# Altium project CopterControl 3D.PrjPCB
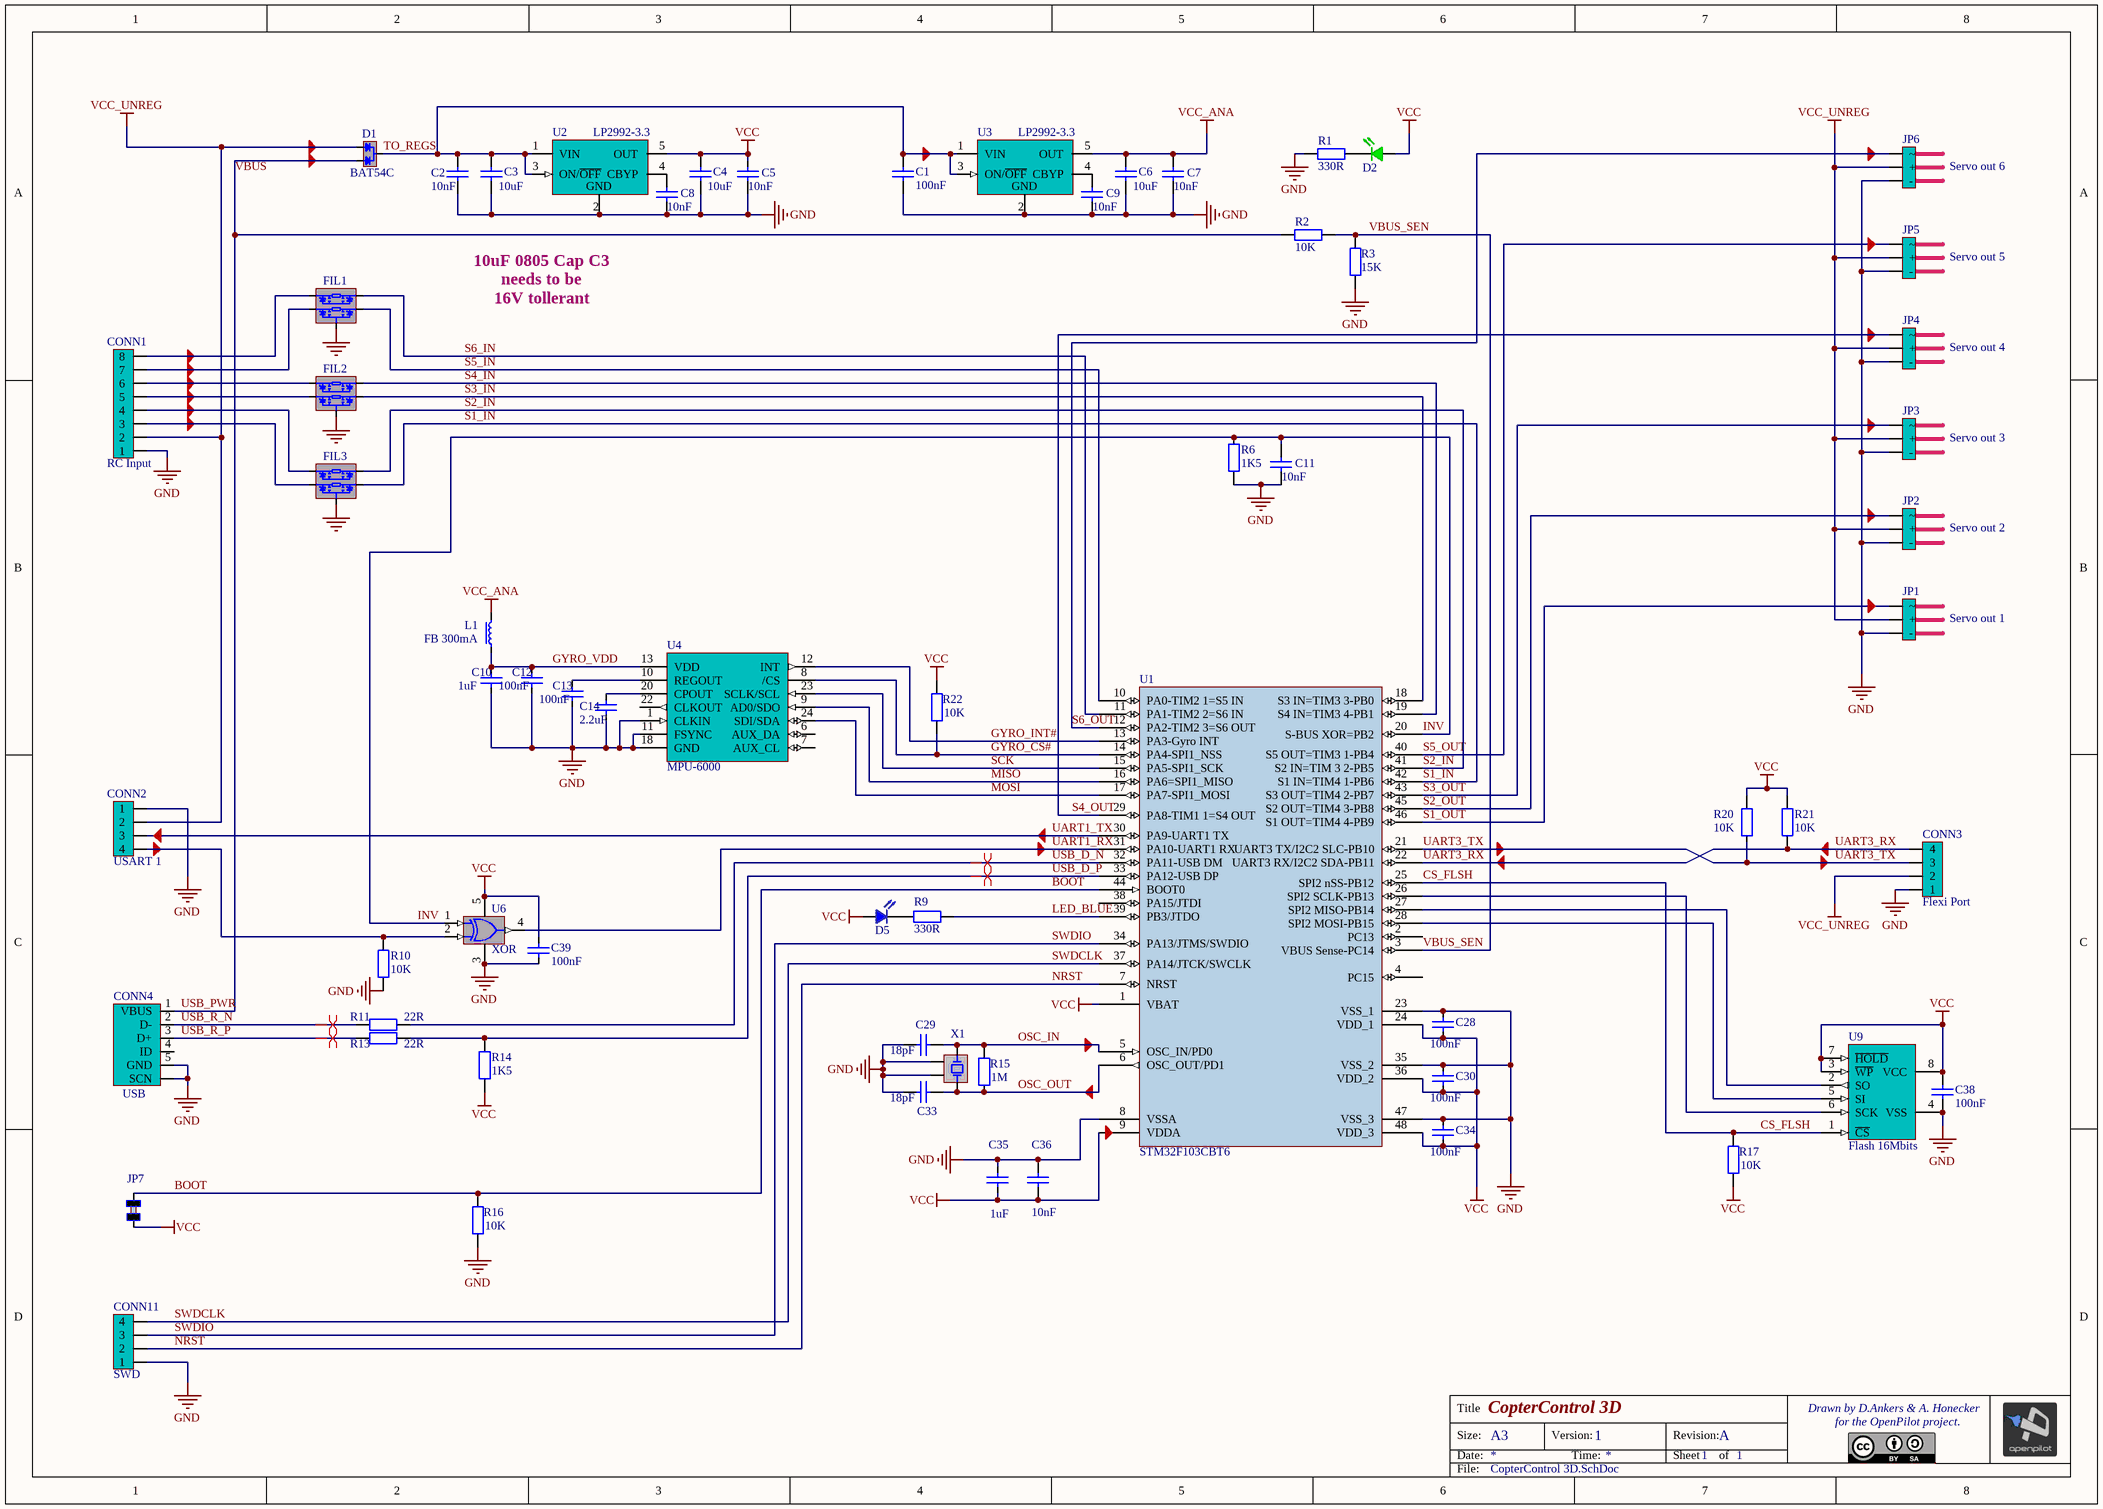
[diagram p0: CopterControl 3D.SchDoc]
1 sheet, 64 parts. Net scope: global (net labels, ports and power ports of the same name join across sheets).
Board file: CopterControl 3D.PcbDoc

## Sheet CopterControl 3D.SchDoc: CopterControl 3D
size A3; Author: David Ankers; DrawnBy: David Ankers; Engineer: David Ankers; Organization: The OpenPilot Project; DocumentNumber: 1; Revision: A; SheetNumber: 1; SheetTotal: 1; License: Creative Commons BY-SA

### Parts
C1  value 100nF  [CAP603N]  (hidden comment: Cap603)
C2  value 10nF  [CAP603L]  (hidden comment: Cap603)
C3  value 10uF  [CAP805L]  (hidden comment: Cap805)
C4  value 10uF  [CAP805L]  (hidden comment: Cap805)
C5  value 10nF  [CAP603N]  (hidden comment: Cap603)
C6  value 10uF  [CAP805L]  (hidden comment: Cap805)
C7  value 10nF  [CAP603N]  (hidden comment: Cap603)
C8  value 10nF  [CAP603N]  (hidden comment: Cap603)
C9  value 10nF  [CAP603N]  (hidden comment: Cap603)
C10  value 1uF  [CAP603L]  (hidden comment: Cap603)
C11  value 10nF  [CAP603N]  (hidden comment: Cap603)
C12  value 100nF  [CAP603L]  (hidden comment: Cap603)
C13  value 100nF  [CAP603L]  (hidden comment: Cap603)
C14  value 2.2uF  [CAP603L]  (hidden comment: Cap603)
C28  value 100nF  [CAP603N]  (hidden comment: Cap603)
C29  value 18pF  [CAP603N]  (hidden comment: Cap603)
C30  value 100nF  [CAP603N]  (hidden comment: Cap603)
C33  value 18pF  [CAP603N]  (hidden comment: Cap603)
C34  value 100nF  [CAP603N]  (hidden comment: Cap603)
C35  value 1uF  [CAP603L]  (hidden comment: Cap603)
C36  value 10nF  [CAP603N]  (hidden comment: Cap603)
C38  value 100nF  [CAP603N]  (hidden comment: Cap603)
C39  value 100nF  [CAP603N]  (hidden comment: Cap603)
CONN1  RC Input  [JST SH 8 Pin Side Entry]
CONN2  USART 1  [JST SH 4 Pin Side Entry]
CONN3  Flexi Port  [JST SH 4 Pin Side Entry]
CONN4  USB  [USB SMD]
CONN11  SWD  [JST SH 4 Pin Side Entry]
D1  BAT54C  [SOT23-3N]
D2  Green  [LED603N]  (value not drawn)
D5  Blue  [LED603N]  (value not drawn)
FIL1  IP4256CZ5-W,115  [SOT-665]  (value not drawn)
FIL2  IP4256CZ5-W,115  [SOT-665]  (value not drawn)
FIL3  IP4256CZ5-W,115  [SOT-665]  (value not drawn)
JP1  Servo out 1  [SIP3 - 0.1]
JP2  Servo out 2  [SIP3 - 0.1]
JP3  Servo out 3  [SIP3 - 0.1]
JP4  Servo out 4  [SIP3 - 0.1]
JP5  Servo out 5  [SIP3 - 0.1]
JP6  Servo out 6  [SIP3 - 0.1]
JP7  2 PAD Touch JMP  [TOUCH JMP 2PAD]  (value not drawn)
L1  FB 300mA  [IND603N]
R1  value 330R  [RES603N]  (hidden comment: Res603)
R2  value 10K  [RES603N]  (hidden comment: Res603)
R3  value 15K  [RES603N]  (hidden comment: Res603)
R6  value 1K5  [RES603N]  (hidden comment: Res603)
R9  value 330R  [RES603N]  (hidden comment: Res603)
R10  value 10K  [RES603N]  (hidden comment: Res603)
R11  value 22R  [RES603N]  (hidden comment: Res603)
R13  value 22R  [RES603N]  (hidden comment: Res603)
R14  value 1K5  [RES603N]  (hidden comment: Res603)
R15  value 1M  [RES603N]  (hidden comment: Res603)
R16  value 10K  [RES603N]  (hidden comment: Res603)
R17  value 10K  [RES603N]  (hidden comment: Res603)
R20  value 10K  [RES603N]  (hidden comment: Res603)
R21  value 10K  [RES603N]  (hidden comment: Res603)
R22  value 10K  [RES603N]  (hidden comment: Res603)
U1  STM32F103CBT6  [STM32 48 Lead]
U2  LP2992-3.3  [SOT23-5L]
U3  LP2992-3.3  [SOT23-5L]
U4  MPU-6000  [IMU-3000]
U6  XOR  [DCK-5]
U9  Flash 16Mbits  [SOIC8_N]
X1  8MHz  [XTAL ACT530SMX-4 Series]  (value not drawn)

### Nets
GND: C1.2 C2.2 C3.2 C4.2 C5.2 C6.2 C7.2 C8.2 C9.2 C10.2 C11.2 C12.2 C13.2 C14.1 C28.1 C29.1 C30.1 C33.1 C34.1 C35.2 C36.1 C38.2 C39.2 CONN1.1 CONN2.1 CONN3.1 CONN4.0(SCN) CONN4.5(GND) CONN11.1 FIL1.2(PAD) FIL2.2(PAD) FIL3.2(PAD) JP1.3(-) JP2.3(-) JP3.3(-) JP4.3(-) JP5.3(-) JP6.3(-) R1.1 R3.1 R6.1 R10.1 R16.1 U1.8(VSSA) U1.23(VSS_1) U1.35(VSS_2) U1.47(VSS_3) U2.2(GND) U3.2(GND) U4.1(CLKIN) U4.11(FSYNC) U4.18(GND) U6.3(GND) U9.4(VSS) X1.2 X1.4
VCC: C4.1 C5.1 C28.2 C30.2 C34.2 C35.1 C36.2 C38.1 C39.1 D2.2(A) D5.2(A) JP7.2 R14.1 R17.1 R20.2 R21.2 R22.2 U1.1(VBAT) U1.9(VDDA) U1.24(VDD_1) U1.36(VDD_2) U1.48(VDD_3) U2.5(OUT) U6.5(VCC) U9.3(~{WP}) U9.7(~{HOLD}) U9.8(VCC)
VCC_ANA: C6.1 C7.1 L1.2 U3.5(OUT)
VCC_UNREG: CONN1.2 CONN2.2 CONN3.2 D1.2(A2) JP1.2(+) JP2.2(+) JP3.2(+) JP4.2(+) JP5.2(+) JP6.2(+)
BOOT: JP7.1 R16.2 U1.44(BOOT0)
CS_FLSH: R17.2 U1.25(SPI2_nSS-PB12) U9.1(~{CS})
GYRO_CS#: R22.1 U1.14(PA4-SPI1_NSS) U4.8(/CS)
GYRO_INT#: U1.13(PA3-Gyro_INT) U4.12(INT)
GYRO_VDD: C10.1 C12.1 L1.1 U4.13(VDD)
INV: C11.1 R6.2 U1.20(S-BUS_XOR=PB2) U6.1(A)
LED_BLUE: R9.2 U1.39(PB3/JTDO)
MISO: U1.16(PA6=SPI1_MISO) U4.9(AD0/SDO)
MOSI: U1.17(PA7-SPI1_MOSI) U4.24(SDI/SDA)
NRST: CONN11.2 U1.7(NRST)
OSC_IN: C29.2 R15.2 U1.5(OSC_IN/PD0) X1.3
OSC_OUT: C33.2 R15.1 U1.6(OSC_OUT/PD1) X1.1
S1_IN: FIL3.5 U1.42(S1_IN=TIM4_1-PB6)
S1_OUT: JP1.1 U1.46(S1_OUT=TIM4_4-PB9)
S2_IN: FIL3.4 U1.41(S2_IN=TIM_3_2-PB5)
S2_OUT: JP2.1 U1.45(S2_OUT=TIM4_3-PB8)
S3_IN: FIL2.5 U1.18(S3_IN=TIM3_3-PB0)
S3_OUT: JP3.1 U1.43(S3_OUT=TIM4_2-PB7)
S4_IN: FIL2.4 U1.19(S4_IN=TIM3_4-PB1)
S4_OUT: JP4.1 U1.29(PA8-TIM1_1=S4_OUT)
S5_IN: FIL1.5 U1.10(PA0-TIM2_1=S5_IN)
S5_OUT: JP5.1 U1.40(S5_OUT=TIM3_1-PB4)
S6_IN: FIL1.4 U1.11(PA1-TIM2_2=S6_IN)
S6_OUT: JP6.1 U1.12(PA2-TIM2_3=S6_OUT)
SCK: U1.15(PA5-SPI1_SCK) U4.23(SCLK/SCL)
SWDCLK: CONN11.4 U1.37(PA14/JTCK/SWCLK)
SWDIO: CONN11.3 U1.34(PA13/JTMS/SWDIO)
TO_REGS: C1.1 C2.1 C3.1 D1.3(COM) U2.1(VIN) U2.3(ON/~{OFF}) U3.1(VIN) U3.3(ON/~{OFF})
UART1_RX: U1.31(PA10-UART1_RX) U6.4(Y)
UART1_TX: CONN2.3 U1.30(PA9-UART1_TX)
UART3_RX: CONN3.4 R21.1 U1.22(UART3_RX/I2C2_SDA-PB11)
UART3_TX: CONN3.3 R20.1 U1.21(UART3_TX/I2C2_SLC-PB10)
USB_D_N: R11.1 U1.32(PA11-USB_DM)
USB_D_P: R13.1 R14.2 U1.33(PA12-USB_DP)
USB_PWR: CONN4.1(VBUS) D1.1(A1) R2.1  [also labelled VBUS]
USB_R_N: CONN4.2(D-) R11.2
USB_R_P: CONN4.3(D+) R13.2
VBUS_SEN: R2.2 R3.2 U1.3(VBUS_Sense-PC14)
NetC8_1: C8.1 U2.4(CBYP)
NetC9_1: C9.1 U3.4(CBYP)
NetC13_1: C13.1 U4.10(REGOUT)
NetC14_2: C14.2 U4.20(CPOUT)
NetCONN1_3: CONN1.3 FIL3.1
NetCONN1_4: CONN1.4 FIL3.3
NetCONN1_5: CONN1.5 FIL2.1
NetCONN1_6: CONN1.6 FIL2.3
NetCONN1_7: CONN1.7 FIL1.1
NetCONN1_8: CONN1.8 FIL1.3
NetCONN2_4: CONN2.4 R10.2 U6.2(B)
NetD2_1: D2.1(K) R1.2
NetD5_1: D5.1(K) R9.1
NetU1_26: U1.26(SPI2_SCLK-PB13) U9.6(SCK)
NetU1_27: U1.27(SPI2_MISO-PB14) U9.2(SO)
NetU1_28: U1.28(SPI2_MOSI-PB15) U9.5(SI)

Not connected (* = marked no-connect by the designer): CONN4 4(ID); U1 2(PC13) 4(PC15) 38(PA15/JTDI); U4 2(NC) 3(NC) 4(NC) 5(NC) 6(AUX_DA) 7(AUX_CL) 14(NC) 15(NC) 16(NC) 17(NC) 19(RESV) 21(RESV) 22(CLKOUT)

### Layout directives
differential pair: USB_D_N, USB_D_P, USB_R_N, USB_R_P

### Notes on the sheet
- 10uF 0805 Cap C3
  needs to be
  16V tollerant
- Title
- Size:
- Date:
- A3
- Version:
- Time:
- Revision:
- Sheet
- of
- Drawn by D.Ankers & A. Honecker
- for the OpenPilot project.
- File:

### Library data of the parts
C1 C2 C5 C7-C14 C28-C30 C33-C36 C38 C39 = Cap603: Capacitor SMD
C3 C4 C6 = Cap805: Capacitor SMD
CONN1 = JST-SH 8-pin Side Entry Socket: Manufacturer: Generic Components; Class: Connector
CONN2 CONN3 CONN11 = JST-SH 4-pin Side Entry Socket: Manufacturer: Generic Components; Class: Connector
CONN4 = USB_SMT_B: USB Type-B SMT Socket; Class: Connector
D1 = BAT54C: Dual Diode Command Cathode
D2 = LED 603 Gr: Green 603 LED; Value: 2.1v 20mA
D5 = LED 603 Bl: Blue 603 LED
FIL1-FIL3 = RF Filter 100R 30pF: IP4256CZ5-W,115 2 channel, 100R, 30pF, RF ESD Filter; Manufacturer: Generic Components; Class: Passive
JP1-JP6 = Hdr 3 Pin 0.1: Header, 3-Pin, 0.1"; Manufacturer: Generic Components; Class: Connector
JP7 = 2 PAD Touch JMP: 2 Pad Touch Jumper
L1 = FerriteBead_300mA: Ferrite Bead 300mA; Manufacturer: Generic Components; Class: Passive
R1-R3 R6 R9-R11 R13-R17 R20-R22 = Res603: Resistor SMD
U1 = STM32F103CBT6: STM32 ARM-based 32-bit MCU with 128 Kbytes Flash, 48-pin LQFP, Industrial Temperature
U2 U3 = LP2985-3.3: 3.3V 250mA LDO Regulator; Manufacturer: National Semiconductor; Manufacturer Part Number: LP2992AIM5-3.3/NOPB; Description: IC REG LDO MICRPWR 250MA SOT23-5; Regulator Topology: Positive Fixed; Voltage - Input: Up to 16V; Voltage - Dropout (Typical): 0.45V @ 250mA; Number of Regulators: 1
U4 = MPU-3/6000: Invensense MPU-3/6000,  3-axis Gyros & Accel on 6000
U6 = XOR SN74LVC1G86DCKR: XOR Gate SN74LVC1G86DCKR
U9 = Flash 16Mb 75MHZ 8SOIC: 16Mbit SPI Flash Memory
X1 = XTAL ACT530SMX-4: Surface Mount Quartz Crystal, Digikey 535-9720-1-ND; Class: Oscillator; SubClass: Crystal Oscillator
